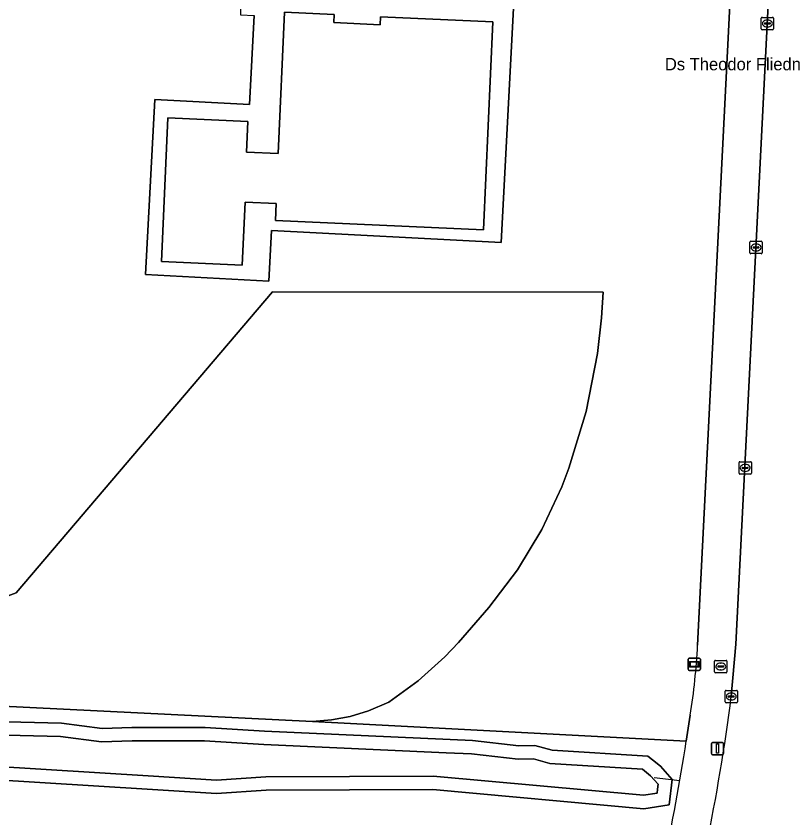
# Model space of a CAD drawing. Extents: x 161758 to 162722, y 384793 to 385405.
# Drawn here: x 162047.5 to 162110.4, y 384884 to 384948.9 of the extents above; entities that cross this region are included whole.
import ezdxf

# ---------------------------------------------------------------- set-up
doc = ezdxf.new("R2010")
doc.units = 0
for name, color, linetype in [('IMGEO_Brandkraan', 7, 'Continuous'), ('IMGEO_Duiker', 7, 'Continuous'), ('IMGEO_Groenvoorziening', 7, 'Continuous'), ('IMGEO_Hek', 7, 'Continuous'), ('IMGEO_Kolk', 7, 'Continuous'), ('IMGEO_Lichtmast', 7, 'Continuous'), ('IMGEO_Loofbos', 7, 'Continuous'), ('IMGEO_Oever', 7, 'Continuous'), ('IMGEO_Openbare_ruimte_label', 7, 'Continuous'), ('IMGEO_Pand', 7, 'Continuous'), ('IMGEO_Rijbaan_lokaal_gesloten', 7, 'Continuous'), ('IMGEO_Verklikker', 7, 'Continuous'), ('IMGEO_Voetpad_open', 7, 'Continuous'), ('IMGEO_Waterloop', 7, 'Continuous')]:
    doc.layers.add(name, color=color, linetype=linetype)

msp = doc.modelspace()

# ---------------------------------------------------------------- linework, layer by layer
at = {"layer": 'IMGEO_Brandkraan'}
for p, q in [((162104.027, 384895.855), (162104.027, 384896.707)), ((162104.102, 384896.781), (162104.954, 384896.781)), ((162104.286, 384896.275), (162104.286, 384896.287)), ((162104.329, 384896.324), (162104.727, 384896.324)), ((162104.515, 384896.561), (162104.54, 384896.561)), ((162104.77, 384896.287), (162104.77, 384896.275)), ((162105.028, 384896.707), (162105.028, 384895.855)), ((162104.954, 384895.781), (162104.102, 384895.781)), ((162104.724, 384896.238), (162104.326, 384896.238)), ((162104.538, 384896.001), (162104.513, 384896.001))]:
    msp.add_line(p, q, dxfattribs=at)
for points in [[(162104.027, 384895.855), (162104.027, 384896.707)], [(162104.102, 384896.781), (162104.954, 384896.781)], [(162105.028, 384896.707), (162105.028, 384895.855)], [(162104.954, 384895.781), (162104.102, 384895.781)]]:
    msp.add_lwpolyline(points, dxfattribs=at)
for centre, radius, start, end in [((162104.104, 384896.705), 0.0765, 91.55205, 178.44795), ((162104.104, 384896.705), 0.0765, 91.55205, 178.44795), ((162104.326, 384896.284), 0.0403, 85.87752, 175.75265), ((162104.323, 384896.274), 0.0366, 178.93798, 274.71019), ((162104.727, 384896.281), 0.043, 264.86636, 352.45326), ((162104.731, 384896.286), 0.0386, 1.73085, 96.63898), ((162104.952, 384896.705), 0.0765, 1.55205, 88.44795), ((162104.952, 384896.705), 0.0765, 1.55205, 88.44795), ((162104.104, 384895.857), 0.0765, 181.55205, 268.44795), ((162104.104, 384895.857), 0.0765, 181.55205, 268.44795), ((162104.952, 384895.857), 0.0765, 271.55205, 358.44795), ((162104.952, 384895.857), 0.0765, 271.55205, 358.44795)]:
    msp.add_arc(centre, radius, start, end, dxfattribs=at)
for centre, major_axis, ratio, start_param, end_param in [((162104.514, 384896.281), (-0.387, 0.002), 0.722429, 4.712389, 7.853982), ((162104.539, 384896.281), (-0.39, 0.002), 0.717154, 1.570796, 4.712389)]:
    msp.add_ellipse(centre, major_axis=major_axis, ratio=ratio, start_param=start_param, end_param=end_param, dxfattribs=at)
at = {"layer": 'IMGEO_Duiker'}
msp.add_lwpolyline([(162099.139, 384887.297), (162101.215, 384887.073)], dxfattribs=at)
at = {"layer": 'IMGEO_Groenvoorziening'}
for points in [[(162105.202, 384948.727), (162105.37, 384952.12), (162105.544, 384954.647), (162105.423, 384954.651)], [(162087.789, 384950.051), (162086.764, 384930.595), (162068.197, 384931.572), (162067.98, 384927.465), (162057.997, 384927.991), (162058.744, 384942.17), (162066.409, 384941.767), (162066.787, 384948.96)], [(162102.654, 384898.009), (162105.202, 384948.727)], [(162025.753, 384894.111), (162047.547, 384902.245), (162068.261, 384926.608), (162095.006, 384926.581), (162094.888, 384924.506), (162094.568, 384921.6), (162093.645, 384916.908), (162092.237, 384912.338), (162091.663, 384910.827), (162090.045, 384907.369), (162088.075, 384904.099), (162085.773, 384901.053), (162083.308, 384898.232), (162082.205, 384897.064), (162080.041, 384895.118), (162077.685, 384893.408), (162076.029, 384892.692), (162074.556, 384892.245), (162073.043, 384891.955), (162071.509, 384891.825), (162101.739, 384890.234), (162102.059, 384892.341)], [(162101.739, 384890.234), (162071.509, 384891.825), (162025.753, 384894.111), (162013.578, 384894.76), (162000, 384895.483), (161940.395, 384898.63), (161890.389, 384901.27), (161887.186, 384893.396), (161885.599, 384889.495)], [(162042.413, 384891.902), (162051.206, 384891.698), (162054.495, 384891.28), (162056.901, 384891.355), (162062.817, 384891.355), (162067.618, 384891.046), (162084.44, 384890.306), (162088.185, 384889.856), (162089.498, 384889.897), (162090.884, 384889.508), (162098.634, 384889.034), (162098.998, 384888.734), (162099.638, 384888.208), (162100.591, 384887.14), (162100.356, 384885.089), (162098.31, 384884.775), (162081.231, 384886.336), (162067.763, 384886.267), (162063.735, 384886.014), (162058.136, 384886.361), (162032.501, 384887.95)]]:
    msp.add_lwpolyline(points, dxfattribs=at)
for centre, radius, start, end in [((162046.268, 384901.063), 56.469, 351.11477, 356.89984), ((161904.894, 384921.269), 199.276, 348.13501, 351.04024)]:
    msp.add_arc(centre, radius, start, end, dxfattribs=at)
at = {"layer": 'IMGEO_Hek'}
msp.add_lwpolyline([(162095.006, 384926.581), (162068.261, 384926.608), (162047.547, 384902.245), (162025.753, 384894.111)], dxfattribs=at)
at = {"layer": 'IMGEO_Kolk'}
for p, q in [((162107.871, 384948.806), (162108.723, 384948.806)), ((162107.796, 384947.88), (162107.796, 384948.732)), ((162108.055, 384948.3), (162108.055, 384948.312)), ((162108.493, 384948.263), (162108.095, 384948.263)), ((162108.098, 384948.349), (162108.496, 384948.349)), ((162108.284, 384948.586), (162108.309, 384948.586)), ((162108.539, 384948.312), (162108.539, 384948.3)), ((162108.797, 384948.732), (162108.797, 384947.88)), ((162108.723, 384947.806), (162107.871, 384947.806)), ((162108.307, 384948.026), (162108.282, 384948.026)), ((162106.953, 384930.685), (162107.805, 384930.685)), ((162106.878, 384929.759), (162106.878, 384930.611)), ((162107.137, 384930.179), (162107.137, 384930.191)), ((162107.575, 384930.142), (162107.177, 384930.142)), ((162107.18, 384930.228), (162107.578, 384930.228)), ((162107.366, 384930.465), (162107.391, 384930.465)), ((162107.621, 384930.191), (162107.621, 384930.179)), ((162107.879, 384930.611), (162107.879, 384929.759)), ((162107.805, 384929.685), (162106.953, 384929.685)), ((162107.389, 384929.905), (162107.364, 384929.905)), ((162106.001, 384911.927), (162106.001, 384912.779)), ((162106.076, 384912.853), (162106.928, 384912.853)), ((162106.489, 384912.633), (162106.514, 384912.633)), ((162107.002, 384912.779), (162107.002, 384911.927)), ((162106.928, 384911.853), (162106.076, 384911.853)), ((162106.26, 384912.347), (162106.26, 384912.359)), ((162106.698, 384912.31), (162106.3, 384912.31)), ((162106.303, 384912.396), (162106.701, 384912.396)), ((162106.512, 384912.073), (162106.487, 384912.073)), ((162106.744, 384912.359), (162106.744, 384912.347)), ((162104.951, 384894.354), (162105.803, 384894.354)), ((162104.876, 384893.428), (162104.876, 384894.28)), ((162105.135, 384893.848), (162105.135, 384893.86)), ((162105.573, 384893.811), (162105.175, 384893.811)), ((162105.178, 384893.897), (162105.576, 384893.897)), ((162105.364, 384894.134), (162105.389, 384894.134)), ((162105.619, 384893.86), (162105.619, 384893.848)), ((162105.877, 384894.28), (162105.877, 384893.428)), ((162105.803, 384893.354), (162104.951, 384893.354)), ((162105.387, 384893.574), (162105.362, 384893.574))]:
    msp.add_line(p, q, dxfattribs=at)
for points in [[(162107.871, 384948.806), (162108.723, 384948.806)], [(162107.796, 384947.88), (162107.796, 384948.732)], [(162108.797, 384948.732), (162108.797, 384947.88)], [(162108.723, 384947.806), (162107.871, 384947.806)], [(162106.953, 384930.685), (162107.805, 384930.685)], [(162106.878, 384929.759), (162106.878, 384930.611)], [(162107.879, 384930.611), (162107.879, 384929.759)], [(162107.805, 384929.685), (162106.953, 384929.685)], [(162106.001, 384911.927), (162106.001, 384912.779)], [(162106.076, 384912.853), (162106.928, 384912.853)], [(162107.002, 384912.779), (162107.002, 384911.927)], [(162106.928, 384911.853), (162106.076, 384911.853)], [(162104.951, 384894.354), (162105.803, 384894.354)], [(162104.876, 384893.428), (162104.876, 384894.28)], [(162105.877, 384894.28), (162105.877, 384893.428)], [(162105.803, 384893.354), (162104.951, 384893.354)]]:
    msp.add_lwpolyline(points, dxfattribs=at)
for centre, radius, start, end in [((162107.873, 384948.73), 0.0765, 91.55205, 178.44795), ((162107.873, 384948.73), 0.0765, 91.55205, 178.44795), ((162108.721, 384948.73), 0.0765, 1.55205, 88.44795), ((162108.721, 384948.73), 0.0765, 1.55205, 88.44795), ((162108.095, 384948.309), 0.0403, 85.87752, 175.75265), ((162108.092, 384948.299), 0.0366, 178.93798, 274.71019), ((162108.496, 384948.306), 0.043, 264.86636, 352.45326), ((162108.5, 384948.311), 0.0386, 1.73085, 96.63898), ((162107.873, 384947.882), 0.0765, 181.55205, 268.44795), ((162107.873, 384947.882), 0.0765, 181.55205, 268.44795), ((162108.721, 384947.882), 0.0765, 271.55205, 358.44795), ((162108.721, 384947.882), 0.0765, 271.55205, 358.44795), ((162106.955, 384930.609), 0.0765, 91.55205, 178.44795), ((162106.955, 384930.609), 0.0765, 91.55205, 178.44795), ((162107.803, 384930.609), 0.0765, 1.55205, 88.44795), ((162107.803, 384930.609), 0.0765, 1.55205, 88.44795), ((162107.177, 384930.188), 0.0403, 85.87752, 175.75265), ((162107.174, 384930.178), 0.0366, 178.93798, 274.71019), ((162107.578, 384930.185), 0.043, 264.86636, 352.45326), ((162107.582, 384930.19), 0.0386, 1.73085, 96.63898), ((162106.955, 384929.761), 0.0765, 181.55205, 268.44795), ((162106.955, 384929.761), 0.0765, 181.55205, 268.44795), ((162107.803, 384929.761), 0.0765, 271.55205, 358.44795), ((162107.803, 384929.761), 0.0765, 271.55205, 358.44795), ((162106.078, 384912.777), 0.0765, 91.55205, 178.44795), ((162106.078, 384912.777), 0.0765, 91.55205, 178.44795), ((162106.926, 384912.777), 0.0765, 1.55205, 88.44795), ((162106.926, 384912.777), 0.0765, 1.55205, 88.44795), ((162106.078, 384911.929), 0.0765, 181.55205, 268.44795), ((162106.078, 384911.929), 0.0765, 181.55205, 268.44795), ((162106.3, 384912.356), 0.0403, 85.87752, 175.75265), ((162106.297, 384912.346), 0.0366, 178.93798, 274.71019), ((162106.701, 384912.353), 0.043, 264.86636, 352.45326), ((162106.705, 384912.358), 0.0386, 1.73085, 96.63898), ((162106.926, 384911.929), 0.0765, 271.55205, 358.44795), ((162106.926, 384911.929), 0.0765, 271.55205, 358.44795), ((162104.953, 384894.278), 0.0765, 91.55205, 178.44795), ((162104.953, 384894.278), 0.0765, 91.55205, 178.44795), ((162105.801, 384894.278), 0.0765, 1.55205, 88.44795), ((162105.801, 384894.278), 0.0765, 1.55205, 88.44795), ((162105.175, 384893.857), 0.0403, 85.87752, 175.75265), ((162105.172, 384893.847), 0.0366, 178.93798, 274.71019), ((162105.576, 384893.854), 0.043, 264.86636, 352.45326), ((162105.58, 384893.859), 0.0386, 1.73085, 96.63898), ((162104.953, 384893.43), 0.0765, 181.55205, 268.44795), ((162104.953, 384893.43), 0.0765, 181.55205, 268.44795), ((162105.801, 384893.43), 0.0765, 271.55205, 358.44795), ((162105.801, 384893.43), 0.0765, 271.55205, 358.44795)]:
    msp.add_arc(centre, radius, start, end, dxfattribs=at)
for centre, major_axis, ratio, start_param, end_param in [((162108.283, 384948.306), (-0.387, 0.002), 0.722429, 4.712389, 7.853982), ((162108.308, 384948.306), (-0.39, 0.002), 0.717154, 1.570796, 4.712389), ((162107.365, 384930.185), (-0.387, 0.002), 0.722429, 4.712389, 7.853982), ((162107.39, 384930.185), (-0.39, 0.002), 0.717154, 1.570796, 4.712389), ((162106.488, 384912.353), (-0.387, 0.002), 0.722429, 4.712389, 7.853982), ((162106.513, 384912.353), (-0.39, 0.002), 0.717154, 1.570796, 4.712389), ((162105.363, 384893.854), (-0.387, 0.002), 0.722429, 4.712389, 7.853982), ((162105.388, 384893.854), (-0.39, 0.002), 0.717154, 1.570796, 4.712389)]:
    msp.add_ellipse(centre, major_axis=major_axis, ratio=ratio, start_param=start_param, end_param=end_param, dxfattribs=at)
at = {"layer": 'IMGEO_Lichtmast'}
for p, q in [((162103.766, 384889.245), (162103.766, 384890.045)), ((162103.766, 384890.045), (162103.766, 384889.245)), ((162103.866, 384890.145), (162104.656, 384890.145)), ((162104.656, 384890.145), (162103.866, 384890.145)), ((162104.756, 384890.045), (162104.756, 384889.245)), ((162104.756, 384889.245), (162104.756, 384890.045)), ((162104.656, 384889.145), (162103.866, 384889.145)), ((162103.866, 384889.145), (162104.656, 384889.145))]:
    msp.add_line(p, q, dxfattribs=at)
msp.add_lwpolyline([(162104.186, 384890.02), (162104.336, 384890.02), (162104.336, 384889.27), (162104.186, 384889.27), (162104.186, 384890.02)], dxfattribs=at)
for centre, start, end in [((162103.866, 384890.045), 90, 180), ((162103.866, 384890.045), 90, 180), ((162104.656, 384890.045), 0, 90), ((162104.656, 384890.045), 360, 90), ((162103.866, 384889.245), 180, 270), ((162103.866, 384889.245), 180, 270), ((162104.656, 384889.245), 270, 0), ((162104.656, 384889.245), 270, 0)]:
    msp.add_arc(centre, 0.1, start, end, dxfattribs=at)
at = {"layer": 'IMGEO_Loofbos'}
msp.add_lwpolyline([(162095.006, 384926.581), (162068.261, 384926.608), (162047.547, 384902.245), (162025.753, 384894.111), (162071.509, 384891.825), (162073.043, 384891.955), (162074.556, 384892.245), (162076.029, 384892.692), (162077.685, 384893.408), (162080.041, 384895.118), (162082.205, 384897.064), (162083.308, 384898.232), (162085.773, 384901.053), (162088.075, 384904.099), (162090.045, 384907.369), (162091.663, 384910.827), (162092.237, 384912.338), (162093.645, 384916.908), (162094.568, 384921.6), (162094.888, 384924.506)], close=True, dxfattribs=at)
at = {"layer": 'IMGEO_Oever'}
for points in [[(162032.501, 384887.95), (162058.136, 384886.361), (162063.735, 384886.014), (162067.763, 384886.267), (162081.231, 384886.336), (162098.31, 384884.775), (162100.356, 384885.089), (162100.591, 384887.14), (162099.638, 384888.208), (162098.998, 384888.734), (162098.634, 384889.034), (162090.884, 384889.508), (162089.498, 384889.897), (162088.185, 384889.856), (162084.44, 384890.306), (162067.618, 384891.046), (162062.817, 384891.355), (162056.901, 384891.355), (162054.495, 384891.28), (162051.206, 384891.698), (162042.413, 384891.902)], [(162042.382, 384890.849), (162051.124, 384890.619), (162054.443, 384890.197), (162056.918, 384890.273), (162062.782, 384890.273), (162067.56, 384889.967), (162082.32, 384889.296), (162084.352, 384889.228), (162088.138, 384888.773), (162089.366, 384888.811), (162090.703, 384888.436), (162098.206, 384887.977), (162098.849, 384887.426), (162099.46, 384886.769), (162099.414, 384886.366), (162099.376, 384886.033), (162098.277, 384885.864), (162081.277, 384887.418), (162067.726, 384887.348), (162063.734, 384887.098), (162058.203, 384887.44), (162032.568, 384889.029)]]:
    msp.add_lwpolyline(points, dxfattribs=at)
at = {"layer": 'IMGEO_Pand'}
msp.add_lwpolyline([(162066.045, 384933.852), (162068.571, 384933.738), (162068.51, 384932.381), (162085.325, 384931.62), (162086.087, 384948.432), (162077.01, 384948.843), (162076.981, 384948.205), (162073.219, 384948.375), (162073.248, 384949.032), (162069.241, 384949.213), (162068.723, 384937.783), (162066.157, 384937.9), (162066.269, 384940.376), (162059.817, 384940.668), (162059.291, 384929.054), (162065.814, 384928.759)], close=True, dxfattribs=at)
at = {"layer": 'IMGEO_Rijbaan_lokaal_gesloten'}
msp.add_lwpolyline([(162115.526, 384963.307), (162117.175, 384996.297), (162117.614, 385005.336), (162117.747, 385009.289), (162119.341, 385039.804), (162119.581, 385044.789), (162119.917, 385051.572), (162113.455, 385051.843), (162112.559, 385034.271), (162111.156, 385004.7), (162109.542, 384973.613), (162108.474, 384951.964), (162105.756, 384898.085), (162105.377, 384893.854)], dxfattribs=at)
msp.add_arc((161932.442, 384916.327), 174.39, 348.56246, 352.59578, dxfattribs=at)
at = {"layer": 'IMGEO_Verklikker'}
for p, q in [((162101.983, 384896.966), (162102.773, 384896.966)), ((162102.773, 384896.966), (162101.983, 384896.966)), ((162101.883, 384896.066), (162101.883, 384896.866)), ((162101.883, 384896.866), (162101.883, 384896.066)), ((162102.873, 384896.866), (162102.873, 384896.066)), ((162102.873, 384896.066), (162102.873, 384896.866)), ((162102.773, 384895.966), (162101.983, 384895.966)), ((162101.983, 384895.966), (162102.773, 384895.966))]:
    msp.add_line(p, q, dxfattribs=at)
for points in [[(162101.984, 384896.698), (162102.772, 384896.698), (162102.772, 384896.234), (162101.984, 384896.234), (162101.984, 384896.698)], [(162102.049, 384896.633), (162102.049, 384896.299), (162102.707, 384896.299), (162102.707, 384896.633), (162102.049, 384896.633)]]:
    msp.add_lwpolyline(points, dxfattribs=at)
for centre, start, end in [((162101.983, 384896.866), 90, 180), ((162101.983, 384896.866), 90, 180), ((162102.773, 384896.866), 0, 90), ((162102.773, 384896.866), 360, 90), ((162101.983, 384896.066), 180, 270), ((162101.983, 384896.066), 180, 270), ((162102.773, 384896.066), 270, 0), ((162102.773, 384896.066), 270, 0)]:
    msp.add_arc(centre, 0.1, start, end, dxfattribs=at)
at = {"layer": 'IMGEO_Voetpad_open'}
for points in [[(162086.087, 384954.2), (162078.205, 384954.615), (162078.417, 384959.06), (162076.608, 384959.146), (162076.394, 384959.154), (162076.237, 384954.719), (162067.116, 384955.199), (162065.836, 384955.267), (162065.81, 384954.232), (162065.744, 384951.575), (162065.68, 384949.018), (162066.787, 384948.96), (162066.409, 384941.767), (162058.744, 384942.17), (162057.997, 384927.991), (162067.98, 384927.465), (162068.197, 384931.572), (162086.764, 384930.595), (162087.789, 384950.051), (162085.874, 384950.152)], [(162076.981, 384948.205), (162077.01, 384948.843), (162086.087, 384948.432), (162085.325, 384931.62), (162068.51, 384932.381), (162068.571, 384933.738), (162066.045, 384933.852), (162065.814, 384928.759), (162059.291, 384929.054), (162059.817, 384940.668), (162066.269, 384940.376), (162066.157, 384937.9), (162068.723, 384937.783), (162069.241, 384949.213), (162073.248, 384949.032), (162073.219, 384948.375)]]:
    msp.add_lwpolyline(points, close=True, dxfattribs=at)
for points in [[(162108.474, 384951.964), (162105.37, 384952.12), (162105.202, 384948.727), (162102.654, 384898.009)], [(162105.377, 384893.854), (162105.756, 384898.085), (162108.474, 384951.964)], [(162102.059, 384892.341), (162101.739, 384890.234)]]:
    msp.add_lwpolyline(points, dxfattribs=at)
for centre, radius, start, end in [((162046.268, 384901.063), 56.469, 351.11477, 356.89984), ((161932.442, 384916.327), 174.39, 348.56246, 352.59578), ((161904.894, 384921.269), 199.276, 348.13501, 351.04024)]:
    msp.add_arc(centre, radius, start, end, dxfattribs=at)
at = {"layer": 'IMGEO_Waterloop'}
msp.add_lwpolyline([(162032.568, 384889.029), (162058.203, 384887.44), (162063.734, 384887.098), (162067.726, 384887.348), (162081.277, 384887.418), (162098.277, 384885.864), (162099.376, 384886.033), (162099.414, 384886.366), (162099.46, 384886.769), (162098.849, 384887.426), (162098.206, 384887.977), (162090.703, 384888.436), (162089.366, 384888.811), (162088.138, 384888.773), (162084.352, 384889.228), (162082.32, 384889.296), (162067.56, 384889.967), (162062.782, 384890.273), (162056.918, 384890.273), (162054.443, 384890.197), (162051.124, 384890.619), (162042.382, 384890.849)], dxfattribs=at)

# ---------------------------------------------------------------- texts
at = {"layer": 'IMGEO_Openbare_ruimte_label'}
msp.add_text('Ds Theodor Fliednerstraat', height=1, dxfattribs=at).set_placement((162100.007, 384944.52))

doc.saveas('drawing.dxf')
